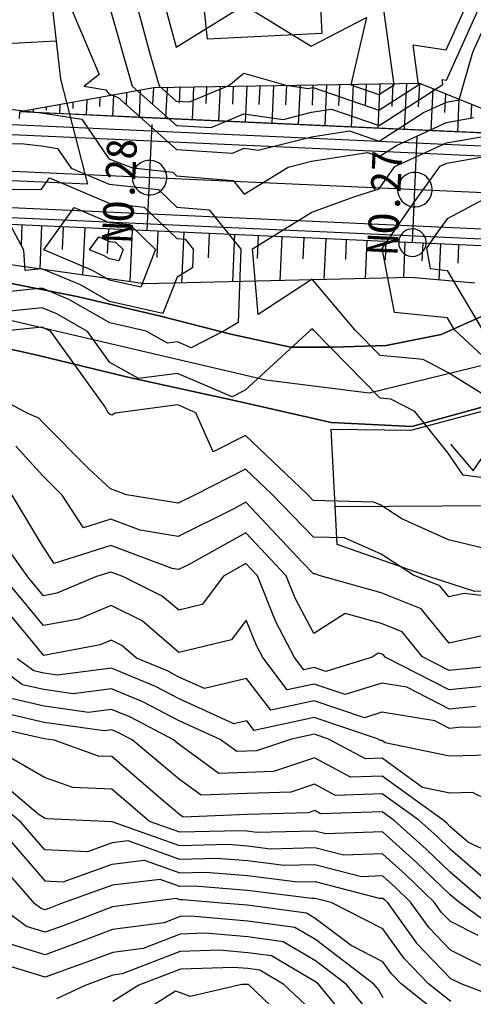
# Model space of a CAD drawing. Extents: x 42655 to 43811, y -141820 to -141156.
# Drawn here: x 43518.5 to 43552.6, y -141406.3 to -141332.6 of the extents above; entities that cross this region are included whole.
import ezdxf

# ---------------------------------------------------------------- set-up
doc = ezdxf.new("R2010")
doc.units = 0
for name, color, linetype in [('D-BMK-HTXT_1', 7, 'Continuous'), ('D-BMK_1', 7, 'Continuous'), ('D-STR', 7, 'Continuous'), ('D-STR-STR4_1', 7, 'Continuous'), ('D-STR-STR5_1', 7, 'Continuous'), ('D-STR_1', 7, 'Continuous'), ('ZE_HICN', 7, 'Continuous'), ('ZE_LWCN', 7, 'Continuous'), ('地形', 7, 'Continuous'), ('現況水路ﾊｯﾁ', 7, 'Continuous')]:
    doc.layers.add(name, color=color, linetype=linetype)

msp = doc.modelspace()

# ---------------------------------------------------------------- linework, layer by layer
at = {"layer": 'D-BMK-HTXT_1'}
for p, q in [((43528.066, -141348.549), (43528.429, -141340.557)), ((43548.046, -141349.456), (43548.409, -141341.464))]:
    msp.add_line(p, q, dxfattribs=at)
for points in [[(43526.948, -141344.553), (43526.969, -141344.785), (43527.031, -141345.01), (43527.132, -141345.22), (43527.269, -141345.408), (43527.437, -141345.569), (43527.632, -141345.698), (43527.846, -141345.789), (43528.073, -141345.841), (43528.306, -141345.852), (43528.537, -141345.82), (43528.759, -141345.748), (43528.964, -141345.638), (43529.146, -141345.493), (43529.299, -141345.317), (43529.419, -141345.117), (43529.501, -141344.899), (43529.543, -141344.67), (43529.543, -141344.436), (43529.501, -141344.207), (43529.419, -141343.989), (43529.299, -141343.789), (43529.146, -141343.613), (43528.964, -141343.468), (43528.759, -141343.358), (43528.537, -141343.286), (43528.306, -141343.254), (43528.073, -141343.265), (43527.846, -141343.317), (43527.632, -141343.408), (43527.437, -141343.537), (43527.269, -141343.698), (43527.132, -141343.886), (43527.031, -141344.096), (43526.969, -141344.321), (43526.948, -141344.553)], [(43546.927, -141345.46), (43546.948, -141345.692), (43547.01, -141345.917), (43547.111, -141346.127), (43547.248, -141346.316), (43547.417, -141346.477), (43547.611, -141346.605), (43547.825, -141346.697), (43548.053, -141346.749), (43548.286, -141346.759), (43548.516, -141346.728), (43548.738, -141346.656), (43548.943, -141346.545), (43549.126, -141346.4), (43549.279, -141346.224), (43549.398, -141346.024), (43549.48, -141345.806), (43549.522, -141345.577), (43549.522, -141345.344), (43549.48, -141345.114), (43549.398, -141344.896), (43549.279, -141344.696), (43549.126, -141344.521), (43548.943, -141344.375), (43548.738, -141344.265), (43548.516, -141344.193), (43548.285, -141344.162), (43548.053, -141344.172), (43547.825, -141344.224), (43547.611, -141344.316), (43547.417, -141344.444), (43547.248, -141344.605), (43547.111, -141344.794), (43547.01, -141345.004), (43546.948, -141345.228), (43546.927, -141345.46)]]:
    msp.add_lwpolyline(points, dxfattribs=at)
at = {"layer": 'D-BMK_1'}
msp.add_lwpolyline([(43648.124, -141349.997), (43439.808, -141340.537)], dxfattribs=at)
at = {"layer": 'D-STR'}
msp.add_lwpolyline([(43547.013, -141349.456), (43547.029, -141349.641), (43547.079, -141349.819), (43547.159, -141349.986), (43547.268, -141350.136), (43547.402, -141350.264), (43547.556, -141350.366), (43547.727, -141350.439), (43547.907, -141350.48), (43548.092, -141350.488), (43548.276, -141350.463), (43548.452, -141350.406), (43548.615, -141350.318), (43548.76, -141350.203), (43548.881, -141350.063), (43548.976, -141349.904), (43549.041, -141349.731), (43549.075, -141349.549), (43549.075, -141349.364), (43549.041, -141349.181), (43548.976, -141349.008), (43548.881, -141348.849), (43548.76, -141348.71), (43548.615, -141348.594), (43548.452, -141348.506), (43548.276, -141348.449), (43548.092, -141348.424), (43547.907, -141348.433), (43547.726, -141348.474), (43547.556, -141348.547), (43547.402, -141348.649), (43547.268, -141348.777), (43547.159, -141348.926), (43547.079, -141349.093), (43547.029, -141349.272), (43547.013, -141349.456)], dxfattribs=at)
at = {"layer": 'D-STR-STR4_1'}
for p, q in [((43518.631, -141348.12), (43518.56, -141349.675)), ((43520.114, -141348.188), (43519.967, -141351.439)), ((43521.74, -141348.262), (43521.662, -141349.965)), ((43523.365, -141348.335), (43523.203, -141351.896)), ((43525.146, -141348.416), (43525.061, -141350.282)), ((43526.926, -141348.497), (43526.749, -141352.398)), ((43528.877, -141348.586), (43528.787, -141350.563)), ((43530.827, -141348.674), (43530.653, -141352.494)), ((43532.737, -141348.761), (43532.653, -141350.606)), ((43534.647, -141348.848), (43534.485, -141352.406)), ((43536.426, -141348.929), (43536.348, -141350.647)), ((43538.205, -141349.009), (43538.055, -141352.323)), ((43539.862, -141349.085), (43539.789, -141350.685)), ((43541.519, -141349.16), (43541.379, -141352.246)), ((43543.062, -141349.23), (43542.994, -141350.72)), ((43544.605, -141349.3), (43544.475, -141352.175)), ((43546.043, -141349.365), (43545.98, -141350.753)), ((43547.48, -141349.431), (43547.358, -141352.108)), ((43548.819, -141349.491), (43548.758, -141350.827)), ((43550.157, -141349.552), (43550.033, -141352.278)), ((43551.52, -141349.614), (43551.457, -141351.005))]:
    msp.add_line(p, q, dxfattribs=at)
msp.add_lwpolyline([(43552.755, -141352.515), (43547.926, -141352.095), (43527.884, -141352.559), (43507.991, -141349.745), (43507.45, -141349.776)], dxfattribs=at)
at = {"layer": 'D-STR-STR5_1'}
for p, q in [((43528.502, -141338.957), (43528.556, -141337.773)), ((43529.557, -141337.757), (43529.451, -141340.103)), ((43530.504, -141338.945), (43530.559, -141337.742)), ((43531.561, -141337.726), (43531.449, -141340.194)), ((43532.505, -141338.975), (43532.563, -141337.71)), ((43533.564, -141337.694), (43533.447, -141340.284)), ((43534.506, -141339.004), (43534.566, -141337.679)), ((43535.568, -141337.663), (43535.445, -141340.375)), ((43536.507, -141339.034), (43536.57, -141337.647)), ((43537.571, -141337.632), (43537.443, -141340.466)), ((43538.507, -141339.064), (43538.573, -141337.616)), ((43539.575, -141337.6), (43539.441, -141340.557)), ((43540.508, -141339.093), (43540.577, -141337.584)), ((43541.578, -141337.569), (43541.439, -141340.647)), ((43542.509, -141339.123), (43542.58, -141337.553)), ((43543.582, -141337.537), (43543.436, -141340.738)), ((43544.51, -141339.152), (43544.584, -141337.521)), ((43545.585, -141337.506), (43545.434, -141340.829)), ((43546.51, -141339.182), (43546.587, -141337.49)), ((43547.589, -141337.474), (43547.432, -141340.92)), ((43548.511, -141339.212), (43548.591, -141337.459)), ((43524.487, -141339.191), (43524.518, -141338.505)), ((43525.528, -141338.322), (43525.455, -141339.922)), ((43526.495, -141339.053), (43526.537, -141338.139)), ((43527.546, -141337.956), (43527.453, -141340.012)), ((43549.574, -141337.855), (43549.43, -141341.01)), ((43550.493, -141339.653), (43550.557, -141338.251)), ((43520.471, -141339.466), (43520.481, -141339.238)), ((43521.49, -141339.055), (43521.459, -141339.74)), ((43522.479, -141339.329), (43522.5, -141338.872)), ((43523.509, -141338.689), (43523.457, -141339.831)), ((43551.54, -141338.647), (43551.428, -141341.101)), ((43552.475, -141340.095), (43552.523, -141339.043)), ((43519.472, -141339.421), (43519.461, -141339.649))]:
    msp.add_line(p, q, dxfattribs=at)
for points in [[(43558.421, -141341.419), (43548.591, -141337.459), (43528.556, -141337.773), (43518.462, -141339.604)], [(43558.421, -141341.419), (43548.431, -141340.965), (43528.452, -141340.058), (43518.462, -141339.604)]]:
    msp.add_lwpolyline(points, dxfattribs=at)
at = {"layer": 'D-STR_1'}
for p in [(43518.44, -141340.104), (43558.421, -141341.419)]:
    msp.add_line(p, (43518.462, -141339.604), dxfattribs=at)
for points in [[(43648.283, -141346.5), (43439.967, -141337.04)], [(43648.249, -141347.25), (43439.933, -141337.79)], [(43647.999, -141352.744), (43439.683, -141343.284)], [(43647.965, -141353.493), (43439.649, -141344.033)], [(43647.943, -141353.993), (43439.627, -141344.533)]]:
    msp.add_lwpolyline(points, dxfattribs=at)
at = {"layer": 'ZE_HICN'}
for points in [[(43529.361, -141331.473), (43530.235, -141334.709), (43535.048, -141331.762)], [(43535.42, -141331.58), (43540.411, -141334.635), (43544.593, -141332.485), (43543.404, -141337.569), (43545.516, -141338.295), (43546.67, -141337.554), (43545.901, -141331.897)], [(43555.398, -141362.163), (43550.703, -141359.233), (43548.855, -141358.265), (43545.609, -141357.973), (43543.727, -141356.056), (43540.494, -141352.201), (43536.423, -141354.874), (43535.985, -141349.93), (43538.968, -141348.091), (43540.47, -141347.165), (43543.697, -141345.978), (43545.55, -141345.394), (43546.177, -141344.484), (43546.729, -141343.716), (43550.621, -141341.931), (43553.796, -141341.368)], [(43515.005, -141341.998), (43518.55, -141341.982), (43520.094, -141342.164), (43521.316, -141342.357), (43522.33, -141343.832), (43525.196, -141345.054), (43528.919, -141345.456), (43530.292, -141346.781), (43532.737, -141346.986), (43535.108, -141349.934), (43534.909, -141355.477), (43533.867, -141356.103), (43531.384, -141357.377), (43530.34, -141356.928), (43529.595, -141357.026)], [(43529.595, -141357.026), (43527.998, -141356.131), (43525.245, -141355.5), (43522.153, -141353.73), (43520.145, -141352.888), (43517.555, -141353.155)], [(43555.389, -141381.266), (43550.81, -141381.708), (43548.809, -141380.683), (43547.276, -141378.791), (43545.705, -141378.158), (43542.971, -141377.403), (43540.621, -141378.928), (43539.211, -141376.257), (43538.543, -141374.569), (43535.496, -141371.34), (43531.117, -141373.76), (43530.421, -141374.106), (43529.941, -141374.028), (43525.325, -141372.298), (43521.065, -141373.656), (43520.237, -141372.398), (43517.892, -141368.504)], [(43555.95, -141392.574), (43552.565, -141390.917), (43550.854, -141390.963), (43548.811, -141390.536), (43545.753, -141388.326), (43544.515, -141388.365), (43541.727, -141386.879), (43540.657, -141386.519), (43538.922, -141386.892), (43536.296, -141387.778), (43535.574, -141387.8), (43534.817, -141387.829), (43533.564, -141386.918), (43530.475, -141385.511), (43527.744, -141384.082), (43525.376, -141383.091), (43522.485, -141383.467), (43520.288, -141383.157), (43518.67, -141382.783), (43516.003, -141380.838)], [(43552.995, -141401.682), (43550.9, -141400.642), (43550.242, -141399.957), (43549.674, -141399.167), (43547.52, -141397.088), (43545.787, -141395.537), (43542.856, -141395.647), (43540.697, -141395.088), (43537.35, -141395.171), (43535.608, -141394.95), (43534.158, -141394.834), (43530.52, -141394.931), (43525.423, -141393.119), (43520.529, -141392.906), (43520.334, -141392.836), (43519.843, -141392.553), (43515.226, -141388.618)], [(43545.839, -141406.396), (43545.489, -141405.769), (43545.146, -141405.351), (43540.73, -141402.003), (43539.18, -141401.089), (43535.635, -141400.607), (43531.356, -141400.235), (43530.545, -141400.262), (43529.339, -141400.727), (43525.462, -141401.244), (43522.825, -141402.257), (43520.383, -141403.142), (43517.852, -141402.378)]]:
    msp.add_lwpolyline(points, dxfattribs=at)
at = {"layer": 'ZE_LWCN'}
for points in [[(43522.215, -141331.507), (43524.438, -141336.789), (43523.31, -141337.665), (43524.943, -141337.922), (43525.163, -141338.243), (43525.875, -141338.512), (43530.271, -141342.441), (43534.481, -141342.709), (43535.359, -141342.34), (43536.412, -141342.491), (43540.443, -141341.465), (43543.296, -141341.028), (43545.533, -141341.796), (43548.867, -141339.655), (43550.607, -141338.857), (43551.561, -141338.688), (43551.88, -141337.529), (43552.605, -141335.083), (43554.285, -141331.355)], [(43525.193, -141331.568), (43526.944, -141337.647), (43530.263, -141340.613), (43532.871, -141340.778), (43535.347, -141339.74), (43538.314, -141340.165), (43540.434, -141339.625), (43541.935, -141339.396), (43545.527, -141340.629), (43550.343, -141337.537), (43550.293, -141337.167), (43550.599, -141337.213), (43553.236, -141331.36)], [(43527.267, -141331.483), (43528.295, -141335.288), (43528.971, -141337.638), (43530.254, -141338.784), (43531.262, -141338.848), (43534.206, -141337.613), (43535.332, -141336.683), (43538.495, -141337.593), (43540.215, -141337.839), (43540.426, -141337.786), (43540.574, -141337.763), (43545.522, -141339.462), (43548.507, -141337.545), (43548.097, -141334.532), (43550.588, -141334.914), (43552.187, -141331.365)], [(43516.235, -141339.204), (43520.082, -141339.659), (43523.13, -141340.139), (43525.186, -141343.134), (43526.97, -141343.81), (43529.997, -141344.137), (43530.281, -141344.411), (43534.55, -141344.768), (43535.375, -141345.794), (43536.484, -141345.111), (43538.684, -141343.755), (43540.452, -141343.305), (43544.657, -141342.661), (43545.538, -141342.963), (43546.852, -141342.12), (43550.614, -141340.394), (43552.679, -141340.028)], [(43555.797, -141360.311), (43551.21, -141356.02), (43550.684, -141355.127), (43546.682, -141354.724), (43545.771, -141349.884), (43547.992, -141346.661), (43550.121, -141343.7), (43550.629, -141343.467), (43554.913, -141342.709)], [(43518.869, -141351.548), (43518.77, -141350.012), (43516.323, -141345.437), (43520.109, -141345.419), (43520.713, -141344.577), (43525.202, -141346.49), (43527.84, -141346.776), (43530.303, -141349.151), (43530.923, -141349.203), (43531.525, -141349.951), (43531.475, -141351.358), (43530.317, -141352.052), (43529.243, -141354.808), (43525.237, -141353.891), (43523.047, -141352.637), (43520.138, -141351.417), (43518.869, -141351.548)], [(43553.829, -141345.983), (43550.649, -141347.666), (43549.806, -141348.837), (43549.096, -141349.868), (43549.388, -141351.415), (43550.667, -141351.544), (43553.295, -141356.011)], [(43523.941, -141351.544), (43520.269, -141350.004), (43522.568, -141346.801), (43525.209, -141347.927), (43526.761, -141348.095), (43528.7, -141349.965), (43527.587, -141352.822), (43525.23, -141352.282), (43523.941, -141351.544)], [(43524.835, -141350.451), (43523.731, -141349.988), (43524.422, -141349.025), (43525.216, -141349.363), (43525.683, -141349.414), (43526.266, -141349.976), (43525.931, -141350.835), (43525.222, -141350.673), (43524.835, -141350.451)], [(43555.831, -141367.516), (43551.863, -141366.983), (43550.732, -141365.317), (43548.214, -141362.197), (43546.411, -141361.253), (43545.625, -141361.183), (43540.606, -141356.071), (43540.512, -141355.958), (43540.339, -141356.072), (43535.445, -141360.572), (43534.467, -141361.075), (43530.351, -141359.308), (43527.414, -141359.693), (43525.259, -141358.484), (43523.58, -141356.151), (43521.259, -141354.823), (43520.151, -141354.359), (43516.241, -141354.762)], [(43554.402, -141372.733), (43550.763, -141371.855), (43547.254, -141370.285), (43545.663, -141369.258), (43545.128, -141369.021), (43540.573, -141368.894), (43540.094, -141368.399), (43535.462, -141363.989), (43533.031, -141365.22), (43531.733, -141362.276), (43530.363, -141361.687), (43525.654, -141362.304), (43525.412, -141362.468), (43525.278, -141362.418), (43525.158, -141362.307), (43524.868, -141361.815), (43520.8, -141356.165), (43520.366, -141355.916), (43520.158, -141355.829), (43516.718, -141356.184)], [(43555.873, -141376.391), (43551.932, -141375.898), (43550.784, -141376.156), (43550.11, -141375.325), (43548.119, -141374.523), (43545.68, -141372.948), (43542.919, -141371.722), (43540.586, -141371.657), (43537.444, -141368.411), (43535.474, -141366.536), (43531.717, -141368.438), (43530.398, -141369.096), (43526.504, -141368.463), (43525.304, -141368.02), (43523.669, -141366.504), (43520.192, -141363.015), (43519.896, -141362.689), (43519.066, -141362.336), (43515.091, -141360.192)], [(43554.392, -141378.849), (43550.8, -141379.658), (43548.693, -141377.058), (43545.694, -141375.85), (43541.01, -141374.557), (43540.71, -141374.424), (43540.599, -141374.421), (43539.774, -141373.569), (43535.485, -141369.023), (43534.582, -141369.522), (43530.409, -141371.601), (43527.527, -141371.132), (43525.315, -141370.303), (43523.274, -141370.954), (43521.649, -141368.486), (43520.212, -141367.043), (43518.169, -141364.801)], [(43554.095, -141382.848), (43550.817, -141383.164), (43545.998, -141380.696), (43545.859, -141380.524), (43545.716, -141380.466), (43545.467, -141380.398), (43545, -141380.701), (43541.516, -141381.785), (43540.633, -141381.489), (43539.867, -141381.653), (43539.165, -141380.728), (43537.749, -141378.046), (43536.378, -141374.579), (43535.507, -141373.656), (43533.816, -141374.591), (43532.196, -141376.733), (43530.436, -141377.161), (43529.205, -141376.098), (43526.227, -141374.627), (43525.334, -141374.292), (43524.254, -141374.636), (43521.271, -141375.883), (43520.254, -141376.072), (43519.082, -141374.661), (43515.133, -141369.144)], [(43552.801, -141384.431), (43550.824, -141384.621), (43547.62, -141382.98), (43545.726, -141382.671), (43542.97, -141383.529), (43540.639, -141382.746), (43538.618, -141383.181), (43536.765, -141380.74), (43536.287, -141379.834), (43535.528, -141377.914), (43534.411, -141379.39), (43530.451, -141380.355), (43527.681, -141377.961), (43525.346, -141376.808), (43522.896, -141377.832), (43520.265, -141378.321), (43517.232, -141374.67)], [(43555.918, -141385.938), (43551.507, -141386.013), (43550.831, -141386.078), (43549.735, -141385.517), (43545.737, -141384.864), (43544.423, -141385.273), (43540.645, -141384.004), (43537.369, -141384.708), (43535.548, -141382.31), (43532.38, -141383.081), (43530.46, -141382.207), (43529.632, -141381.774), (43527.268, -141380.785), (43526.157, -141379.825), (43525.358, -141379.43), (43524.52, -141379.78), (43520.276, -141380.57), (43515.382, -141374.678)], [(43554.897, -141388.066), (43550.841, -141388.174), (43545.999, -141387.163), (43545.747, -141386.981), (43545.645, -141386.984), (43545.414, -141386.861), (43540.651, -141385.262), (43536.12, -141386.236), (43535.564, -141385.503), (43534.595, -141385.739), (43530.468, -141383.859), (43528.688, -141382.928), (43525.368, -141381.539), (43521.317, -141382.065), (43520.282, -141381.919), (43519.52, -141381.743), (43518.264, -141380.827)], [(43555.968, -141396.398), (43552.259, -141394.672), (43550.866, -141393.463), (43550.652, -141393.257), (43550.366, -141393.001), (43545.76, -141389.672), (43543.386, -141389.746), (43540.665, -141388.295), (43537.591, -141389.332), (43535.582, -141389.392), (43533.471, -141389.475), (43530.484, -141387.301), (43530.045, -141386.934), (43526.8, -141385.236), (43525.383, -141384.643), (43523.653, -141384.868), (43520.294, -141384.394), (43517.82, -141383.823)], [(43555.431, -141399.139), (43550.874, -141395.184), (43549.869, -141394.214), (43548.522, -141393.009), (43545.766, -141391.018), (43542.257, -141391.127), (43540.674, -141390.283), (43538.887, -141390.886), (43535.59, -141390.985), (43532.126, -141391.12), (43530.496, -141389.934), (43526.924, -141386.949), (43525.857, -141386.391), (43525.39, -141386.196), (43524.822, -141386.27), (43520.3, -141385.632), (43516.969, -141384.863)], [(43553.466, -141399.149), (43550.882, -141396.906), (43549.086, -141395.172), (43546.679, -141393.018), (43545.772, -141392.363), (43541.128, -141392.508), (43540.684, -141392.271), (43540.182, -141392.44), (43535.597, -141392.577), (43530.78, -141392.766), (43530.509, -141392.568), (43529.07, -141391.366), (43525.4, -141388.208), (43524.406, -141388.165), (43521.069, -141386.977), (43520.306, -141386.869), (43516.119, -141385.902)], [(43555.996, -141402.427), (43551.502, -141399.158), (43550.89, -141398.627), (43548.303, -141396.13), (43545.78, -141393.872), (43541.509, -141394.032), (43540.691, -141393.82), (43536.314, -141393.928), (43535.603, -141393.838), (43535.011, -141393.79), (43530.515, -141393.911), (43528.25, -141393.105), (43525.412, -141390.664), (43522.467, -141390.536), (43520.319, -141389.77), (43515.533, -141387.003)], [(43555.967, -141405.299), (43550.91, -141402.79), (43549.298, -141401.111), (43547.907, -141399.175), (43546.737, -141398.045), (43545.795, -141397.203), (43544.202, -141397.263), (43540.703, -141396.356), (43538.386, -141396.413), (43535.614, -141396.063), (43533.305, -141395.877), (43530.525, -141395.952), (43526.63, -141394.567), (43525.431, -141394.715), (43523.577, -141395.377), (43520.345, -141395.244), (43518.539, -141393.151), (43515.234, -141390.335)], [(43516.544, -141393.161), (43520.356, -141397.578), (43521.731, -141397.635), (43525.438, -141396.312), (43527.837, -141396.014), (43530.53, -141396.972), (43532.451, -141396.92), (43535.619, -141397.175), (43539.422, -141397.656), (43540.709, -141397.624), (43545.549, -141398.878), (43545.803, -141398.868), (43545.954, -141399.003), (43546.14, -141399.183), (43548.354, -141402.266), (43550.92, -141404.937), (43551.692, -141405.32), (43554.974, -141406.567)], [(43550.928, -141406.674), (43549.246, -141405.331), (43547.41, -141403.42), (43545.814, -141401.198), (43541.917, -141399.203), (43540.715, -141398.892), (43540.458, -141398.898), (43535.624, -141398.288), (43531.598, -141397.964), (43530.535, -141397.992), (43529.044, -141397.462), (43525.446, -141397.908), (43521.546, -141399.3), (43520.648, -141399.645), (43520.367, -141399.747), (43520.075, -141399.659), (43519.608, -141399.309), (43515.253, -141394.339)], [(43550.936, -141408.322), (43547.203, -141405.341), (43546.466, -141404.574), (43545.826, -141403.683), (43543.419, -141402.451), (43540.722, -141400.406), (43540.058, -141400.015), (43535.629, -141399.412), (43533.672, -141399.242), (43530.745, -141399.007), (43530.539, -141399.012), (43530.251, -141398.91), (43527.327, -141399.272), (43525.454, -141399.522), (43521.736, -141400.951), (43520.375, -141401.445), (43518.964, -141401.019), (43516.701, -141399.323)], [(43544.444, -141407.047), (43543.061, -141405.361), (43540.737, -141403.599), (43538.301, -141402.163), (43535.641, -141401.801), (43532.429, -141401.522), (43530.552, -141401.585), (43527.758, -141402.66), (43525.47, -141402.965), (43523.914, -141403.563), (43520.391, -141404.84), (43516.74, -141403.738)], [(43543.399, -141408.326), (43540.975, -141405.37), (43540.745, -141405.196), (43537.423, -141403.237), (43535.646, -141402.995), (43533.501, -141402.809), (43530.558, -141402.907), (43526.177, -141404.593), (43525.478, -141404.686), (43525.003, -141404.869), (43523.389, -141405.454), (43521.227, -141406.467)], [(43540.757, -141407.657), (43538.363, -141405.383), (43536.545, -141404.311), (43535.652, -141404.189), (43534.574, -141404.096), (43530.564, -141404.23), (43527.433, -141405.435), (43525.488, -141406.676)], [(43540.769, -141410.225), (43535.685, -141405.396), (43535.667, -141405.385), (43535.658, -141405.384), (43535.647, -141405.383), (43535.195, -141405.398), (43531.29, -141406.284), (43530.573, -141406.012), (43530.192, -141405.881), (43525.498, -141408.877)]]:
    msp.add_lwpolyline(points, dxfattribs=at)
at = {"layer": '地形'}
msp.add_line((43542.275, -141369.349), (43563.337, -141369.235), dxfattribs=at)
for points in [[(43522.441, -141321.659), (43531.86, -141321.596), (43531.984, -141320.474), (43539.095, -141320.661), (43539.095, -141326.208), (43540.841, -141326.208), (43541.216, -141333.688), (43532.608, -141334.124), (43532.296, -141331.257), (43522.904, -141331.511), (43522.441, -141321.659)], [(43520.931, -141331.857), (43521.54, -141337.13), (43523.57, -141345.041), (43514.434, -141344.636), (43499.817, -141344.095), (43496.772, -141341.729), (43496.095, -141340.85), (43495.418, -141337.537), (43495.215, -141334.088), (43495.418, -141326.989)], [(43553.691, -141354.812), (43550.208, -141356.373), (43546.065, -141357.213), (43542.041, -141357.333), (43538.86, -141357.323), (43534.355, -141356.365), (43529.057, -141354.989), (43522.883, -141353.53), (43517.334, -141352.446), (43510.743, -141351.321), (43504.861, -141350.612), (43498.353, -141350.279), (43495.141, -141350.071), (43486.185, -141350.513), (43469.214, -141351.337), (43459.314, -141352.162), (43451.654, -141352.339), (43446.055, -141351.102), (43441.223, -141348.158), (43435.118, -141343.288), (43425.795, -141335.807), (43423.686, -141334.529), (43420.559, -141333.955), (43416.507, -141334.688)], [(43495.297, -141333.637), (43496.042, -141335.498), (43496.926, -141336.149), (43502.512, -141335.544), (43509.074, -141334.893), (43521.176, -141334.242)], [(43647.722, -141358.843), (43628.878, -141354.259), (43624.278, -141352.34), (43610.656, -141352.746), (43600.049, -141357.9), (43584.108, -141344.001), (43579.575, -141340.103), (43575.981, -141339.003), (43571.17, -141339.119), (43567.866, -141341.494), (43559.565, -141353.262), (43554.745, -141358.368), (43544.775, -141360.801), (43537.008, -141359.816), (43506.675, -141352.748), (43493.73, -141352.632), (43456.856, -141354.434), (43449.599, -141354.085), (43443.512, -141351.884), (43435.686, -141346.669), (43422.979, -141336.46), (43420.429, -141335.881), (43409.299, -141338.603)], [(43473.328, -141355.68), (43481.912, -141355.153), (43487.41, -141354.889), (43494.79, -141355.077), (43500.588, -141355.002), (43506.364, -141355.206), (43513.341, -141356.494), (43519.788, -141357.934), (43526.614, -141359.602), (43534.957, -141361.42), (43541.934, -141363.012), (43548.002, -141363.315), (43554.828, -141361.42)], [(43559.478, -141359.464), (43560.917, -141363.6), (43561.876, -141363.651), (43562.205, -141364.382), (43564.705, -141374.179), (43556.854, -141375.743), (43552.734, -141375.747), (43549.402, -141374.688), (43542.386, -141372.212), (43541.927, -141363.508), (43547.931, -141363.593), (43554.897, -141361.741), (43558.16, -141359.818), (43559.478, -141359.464)], [(43550.914, -141364.652), (43552.622, -141366.655), (43554.242, -141364.266)]]:
    msp.add_lwpolyline(points, dxfattribs=at)
at = {"layer": '現況水路ﾊｯﾁ'}
for points in [[(43416.507, -141334.688), (43420.559, -141333.955), (43423.686, -141334.529), (43425.795, -141335.807), (43435.118, -141343.288), (43441.223, -141348.158), (43446.055, -141351.102), (43451.654, -141352.339), (43459.314, -141352.162), (43469.214, -141351.337), (43486.185, -141350.513), (43495.141, -141350.071), (43498.353, -141350.279), (43504.861, -141350.612), (43510.743, -141351.321), (43517.334, -141352.446), (43522.883, -141353.53), (43529.057, -141354.989), (43534.355, -141356.365), (43538.86, -141357.323), (43542.041, -141357.333), (43546.065, -141357.213), (43550.208, -141356.373), (43553.691, -141354.812)], [(43554.828, -141361.42), (43548.002, -141363.315), (43541.934, -141363.012), (43534.957, -141361.42), (43526.614, -141359.602), (43519.788, -141357.934), (43513.341, -141356.494), (43506.364, -141355.206), (43500.588, -141355.002), (43494.79, -141355.077), (43487.41, -141354.889), (43481.912, -141355.153), (43473.328, -141355.68)]]:
    msp.add_lwpolyline(points, dxfattribs=at)

# ---------------------------------------------------------------- texts
at = {"layer": 'D-BMK-HTXT_1'}
for s, p in [('NO.28', (43526.947, -141349.499)), ('NO.27', (43546.926, -141350.406))]:
    msp.add_text(s, height=2.3065, rotation=87.39913, dxfattribs=at).set_placement(p)

doc.saveas('drawing.dxf')
